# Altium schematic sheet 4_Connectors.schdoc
size 309 x 223 mm; Symbol: Artery_A4; Device: Artery_A4; Company: Artery Technology; Drawed: SD; Version: 1.0; Page Size: A4; @Project Name: AT-START-F490; @Page Count: 4; @Update Date: 2024-11-26; @Create Date: 2024-11-26; @Schematic Name: AT-START-F490; @Page No: 4; @Page Name: Connectors; @Board Name: AT-START-F490 V1.0; @Create Time: 14:05:45; @Update Time: 14:06:01
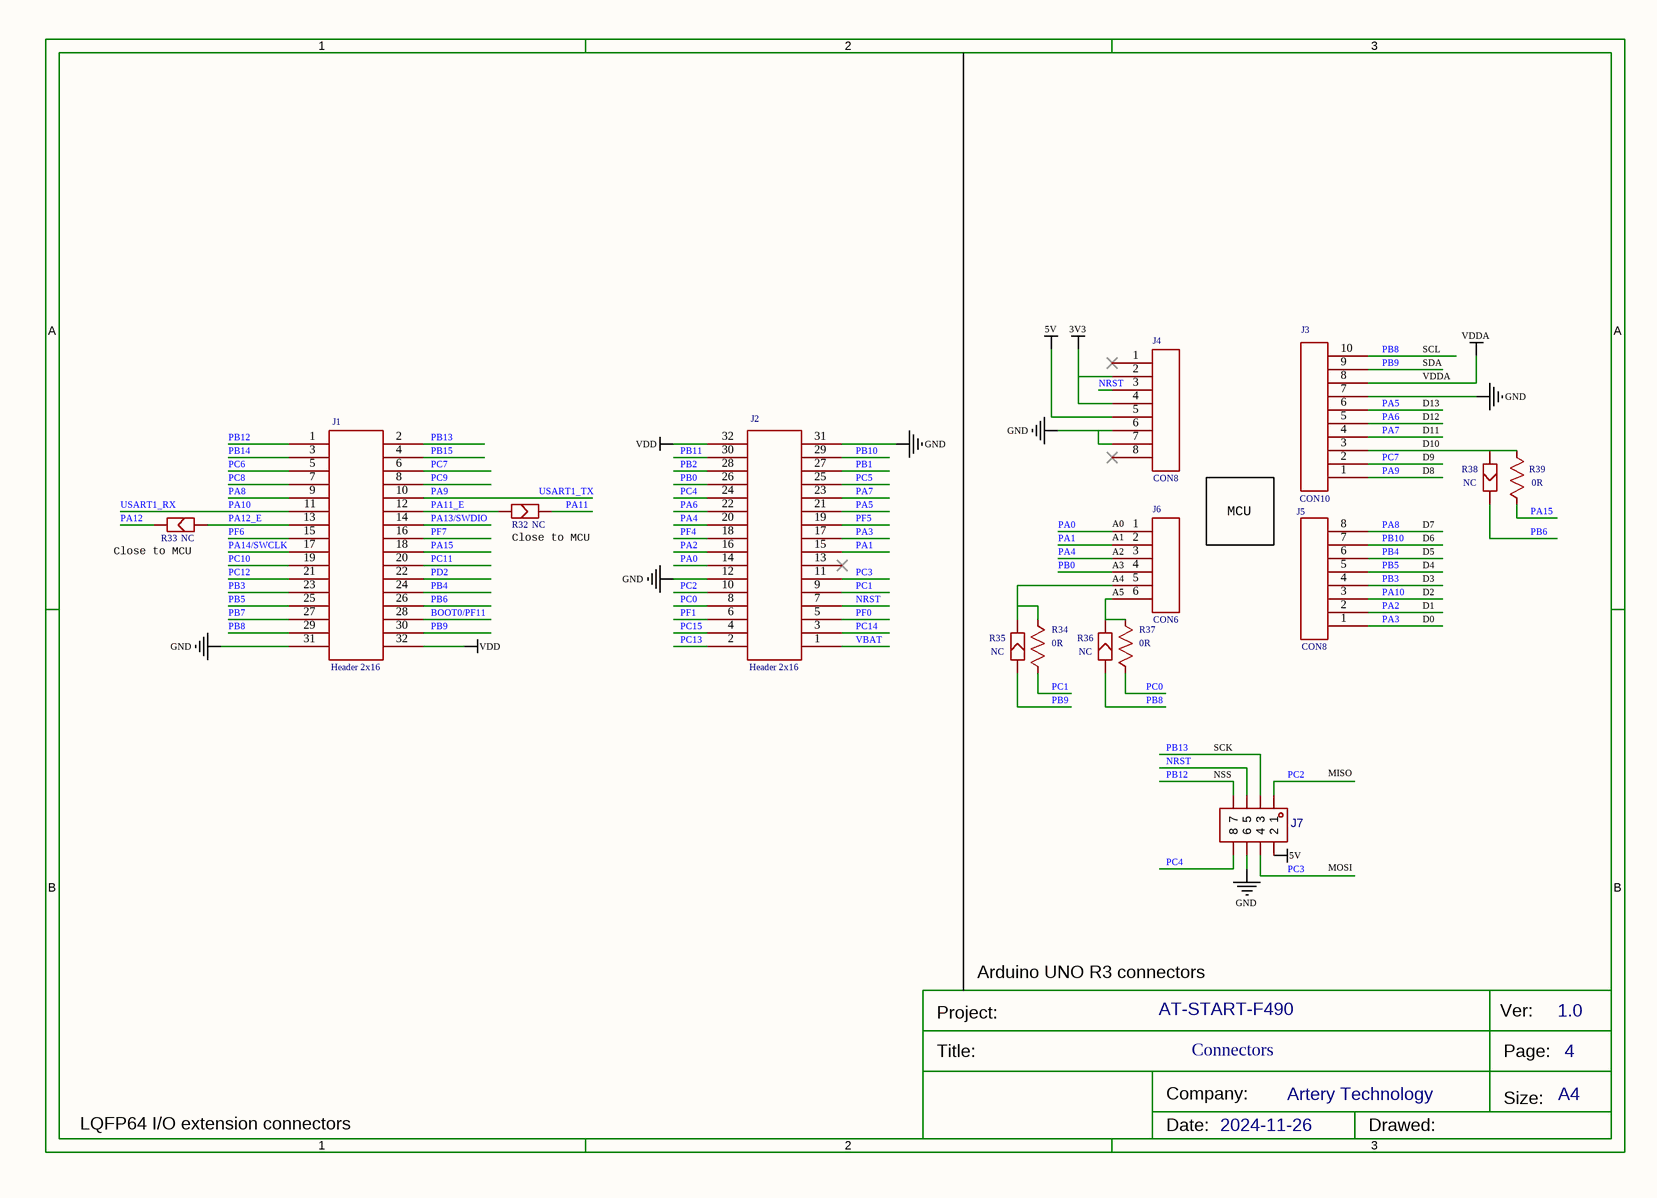
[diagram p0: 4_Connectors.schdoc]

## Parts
J1  Header 2x16  [HDR-M-2.54_2X16]
J2  Header 2x16  [HDR-M-2.54_2X16]
J3  CON10  [FEMALE HEADER 1X10]
J4  CON8  [FEMALE HEADER 1X8]
J5  CON8  [FEMALE HEADER 1X8]
J6  CON6  [FEMALE HEADER 1X6]
J7  Header 4X2  [HDR2X4]  (value not drawn)
R32  NC  [SB-PAD]
R33  NC  [SB-PAD]
R34  0R  [SB-PAD]
R35  NC  [SB-PAD]
R36  NC  [SB-PAD]
R37  0R  [SB-PAD]
R38  NC  [SB-PAD]
R39  0R  [SB-PAD]

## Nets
3V3: J4.2 J4.4
5V: J4.5 J7.2
GND: J1.31 J2.12 J2.31 J3.7 J4.6 J4.7 J7.6
VDD: J1.32 J2.32
VDDA: J3.8
BOOT0/PF11: J1.28
NRST: J2.7 J4.3 J7.5
PA0: J2.14 J6.1
PA1: J2.15 J6.2
PA2: J2.16 J5.2
PA3: J2.17 J5.1
PA4: J2.20 J6.3
PA5: J2.21 J3.6
PA6: J2.22 J3.5
PA7: J2.23 J3.4
PA8: J1.9 J5.8
PA9: J1.10 J3.1  [also labelled USART1_TX]
PA10: J1.11 J5.3  [also labelled USART1_RX]
PA11: R32.2
PA11_E: J1.12 R32.1
PA12: R33.2
PA12_E: J1.13 R33.1
PA13/SWDIO: J1.14
PA14/SWCLK: J1.17
PA15: J1.18 R39.2
PB0: J2.26 J6.4
PB1: J2.27
PB2: J2.28
PB3: J1.23 J5.4
PB4: J1.24 J5.6
PB5: J1.25 J5.5
PB6: J1.26 R38.2
PB7: J1.27
PB8: J1.29 J3.10 R36.1
PB9: J1.30 J3.9 R35.1
PB10: J2.29 J5.7
PB11: J2.30
PB12: J1.1 J7.7
PB13: J1.2 J7.3
PB14: J1.3
PB15: J1.4
PC0: J2.8 R37.1
PC1: J2.9 R34.1
PC2: J2.10 J7.1
PC3: J2.11 J7.4
PC4: J2.24 J7.8
PC5: J2.25
PC6: J1.5
PC7: J1.6 J3.2
PC8: J1.7
PC9: J1.8
PC10: J1.19
PC11: J1.20
PC12: J1.21
PC13: J2.2
PC14: J2.3
PC15: J2.4
PD2: J1.22
PF0: J2.5
PF1: J2.6
PF4: J2.18
PF5: J2.19
PF6: J1.15
PF7: J1.16
VBAT: J2.1
NetJ3_3: J3.3 R38.1 R39.1
NetJ6_5: J6.5 R34.2 R35.2
NetJ6_6: J6.6 R36.2 R37.2

Not connected (* = marked no-connect by the designer): J2 13*; J4 1* 8*

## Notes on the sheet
- SCL
- SDA
- VDDA
- D13
- D8
- D9
- D10
- D11
- D12
- (near R32) Close to MCU
- (near J6) A0
- (near J6) A1
- MCU
- D6
- D7
- (near R33) Close to MCU
- (near J6) A2
- (near J6) A3
- A4
- A5
- D1
- D2
- D3
- D4
- D5
- D0
- SCK
- (near J7) NSS
- MISO
- MOSI
- Arduino UNO R3 connectors
- LQFP64 I/O extension connectors

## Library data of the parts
J1 J2 = Header 2x16: Convert to PCB: yes
J3 = CON10: Convert to PCB: yes
J4 J5 = CON8: Convert to PCB: yes
J6 = CON6: Convert to PCB: yes
J7 = Header 4X2: Convert to PCB: yes
R32 R33 R35 R36 R38 = NC: Convert to PCB: yes
R34 R37 R39 = 0R: Convert to PCB: yes; Origin Footprint: 0603_R-M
